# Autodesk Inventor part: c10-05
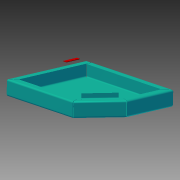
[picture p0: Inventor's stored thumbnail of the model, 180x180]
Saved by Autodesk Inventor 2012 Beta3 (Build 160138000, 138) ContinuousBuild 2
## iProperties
Created: 2011-01
Part Number: c10-05
Material: Steel, Mild
Document SubType Name: Sheet Metal
Designer: Beta-8540w
Density: 7.86 g/cm^3
Sheet Metal Rule: Steel - 16ga
Author: Beta-8540w
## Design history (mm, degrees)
node "Face1"
  sketch "Sketch1"
    geometry: L1 (0, 0)-(240, 0); L2 (240, 0)-(240, 300); L3 (240, 300)-(0, 300); L4 (0, 300)-(0, 0); L5 (140, 300)-(240, 229.979)
    constraints: 10 end point, 2 parallel, 2 point on line, 1 horizontal, 1 perpendicular
    dimensions: "d0" = 240 distance of L3.end L2.end; "d1" = 300 distance of L2.end L1.end; "d2" = 35 deg angle of L3 L5; "d3" = 100 distance from line of L2 L5.start
node "Flange1"
node "Flange2"
workplane "Work Plane1"
node "Flange3"
node "Face2"
  sketch "Sketch4"
    geometry: L1 (0, 15.428)-(214.889, 15.428) reference; L2 (25, 5.428)-(65, 5.428); L3 (65, 5.428)-(65, -4.572); L4 (65, -4.572)-(25, -4.572); L5 (25, -4.572)-(25, 5.428); 1 further point
    constraints: 8 end point, 2 parallel, 1 horizontal, 1 perpendicular
    dimensions: "d27" = 25 distance from line of L5 L1.start; "d28" = 10 distance of L4.end L2.start; "d29" = 40 distance of L3.end L4.end; "d50" = 10 distance between parallel lines of L1 L2
sketch "Sketch5" dims "SeamGap" = 0.01, "Thickness" = 1.524 (derived)
  geometry: L1 (0, 15.428)-(214.889, 15.428) reference; L2 (160, 5.428)-(200, 5.428); L3 (200, 5.428)-(200, -4.572); L4 (200, -4.572)-(160, -4.572); L5 (160, -4.572)-(160, 5.428); 1 further point
  constraints: 8 end point, 2 parallel, 1 horizontal, 1 perpendicular
  dimensions: "d30" = 10 distance of L4.end L2.start (= d28); "d31" = 40 distance of L3.end L4.end (= d29); "d32" = 160 distance from line of L1.start L5; "d51" = 10 distance between parallel lines of L1 L2
body "Solid1"
face "Plate1" dims "Thickness" = 1.524 (derived)
sketch "Sketch2"
  geometry: L1 (0, 40)-(-300, 40); L2 (-300, 40)-(-300, 0); 2 other entities
  constraints: 4 end point, 4 other
face "Plate2" dims "d5" = 1.524 (= BendReliefWidth), "d6" = 0.762 (= BendReliefDepth), "d7" = 3.048 (= MinimumRemnant), "d8" = 3.048 (= BendRadius), "d9" = 40, "d10" = 90 deg, "d11" = 3.048 (= BendRadius), "d12" = 6.096 (= CornerReliefSize), "d13" = 0.762 (= GapSize), "d14" = 3.048 (= JacobiRadiusSize), "SeamGap" = 0.01, "Thickness" = 1.524 (derived)
bend "Bend1" dims "d5" = 1.524 (= BendReliefWidth), "d6" = 0.762 (= BendReliefDepth), "d7" = 3.048 (= MinimumRemnant), "d8" = 3.048 (= BendRadius), "d9" = 40, "d10" = 90 deg, "d11" = 3.048 (= BendRadius), "SeamGap" = 0.01, "Thickness" = 1.524 (derived)
feature "Corner1" dims "d9" = 40, "d10" = 90 deg, "d12" = 6.096 (= CornerReliefSize), "d13" = 0.762 (= GapSize), "d14" = 3.048 (= JacobiRadiusSize)
sketch "Sketch3"
  geometry: L1 (20, 0)-(20, 295.874); L2 (20, 295.874)-(0, 295.874); 2 other entities
  constraints: 4 end point, 4 other
face "Plate3" dims "d15" = 1.524 (= BendReliefWidth), "d16" = 0.762 (= BendReliefDepth), "d17" = 3.048 (= MinimumRemnant), "d18" = 3.048 (= BendRadius), "d19" = 20, "d20" = 90 deg, "d21" = 3.048 (= BendRadius), "d22" = 6.096 (= CornerReliefSize), "d23" = 0.762 (= GapSize), "d24" = 3.048 (= JacobiRadiusSize), "d25" = 10, "SeamGap" = 0.01, "Thickness" = 1.524 (derived)
bend "Bend2" dims "d15" = 1.524 (= BendReliefWidth), "d16" = 0.762 (= BendReliefDepth), "d17" = 3.048 (= MinimumRemnant), "d18" = 3.048 (= BendRadius), "d19" = 20, "d20" = 90 deg, "d21" = 3.048 (= BendRadius), "SeamGap" = 0.01, "Thickness" = 1.524 (derived)
feature "Corner2" dims "d19" = 20, "d20" = 90 deg, "d22" = 6.096 (= CornerReliefSize), "d23" = 0.762 (= GapSize), "d24" = 3.048 (= JacobiRadiusSize)
face "Plate4" dims "d33" = 3.048 (= BendRadius), "d34" = 1.524 (= BendReliefWidth), "d36" = 3.048 (= MinimumRemnant), "Thickness" = 1.524 (derived)
bend "Bend3" dims "d33" = 3.048 (= BendRadius), "d34" = 1.524 (= BendReliefWidth), "d35" = 0.762 (= BendReliefDepth), "d36" = 3.048 (= MinimumRemnant), "d37" = 3.048 (= BendRadius), "SeamGap" = 0.01, "Thickness" = 1.524 (derived)
sketch "Sketch6"
  geometry: L1 (-94.531, 0)-(-10, 0); L2 (-10, 0)-(-10, 15); L3 (-10, 15)-(-94.531, 15); L4 (-94.531, 15)-(-94.531, 0)
  constraints: 8 end point
face "Plate5" dims "d38" = 1.524 (= BendReliefWidth), "d39" = 0.762 (= BendReliefDepth), "d40" = 3.048 (= MinimumRemnant), "d41" = 3.048 (= BendRadius), "d42" = 10, "d43" = 10, "d44" = 15, "d45" = 90 deg, "d46" = 3.048 (= BendRadius), "d47" = 6.096 (= CornerReliefSize), "d48" = 0.762 (= GapSize), "d49" = 3.048 (= JacobiRadiusSize), "SeamGap" = 0.01, "Thickness" = 1.524 (derived)
bend "Bend4" dims "d38" = 1.524 (= BendReliefWidth), "d39" = 0.762 (= BendReliefDepth), "d40" = 3.048 (= MinimumRemnant), "d41" = 3.048 (= BendRadius), "d44" = 15, "d45" = 90 deg, "d46" = 3.048 (= BendRadius), "SeamGap" = 0.01, "Thickness" = 1.524 (derived)
feature "Corner3" dims "d44" = 15, "d45" = 90 deg, "d47" = 6.096 (= CornerReliefSize), "d48" = 0.762 (= GapSize), "d49" = 3.048 (= JacobiRadiusSize)
other parameters: "BendRadius" = 3.048 (= 2 x Thickness), "BendReliefWidth" = 1.524 (= Thickness), "BendReliefDepth" = 0.762 (= 0.5 x Thickness), "CornerReliefSize" = 6.096 (= 4 x Thickness), "MinimumRemnant" = 3.048 (= 2 x Thickness), "TransitionRadius" = 3.048 (= BendRadius), "JacobiRadiusSize" = 3.048 (= BendRadius), "GapSize" = 0.762 (= 0.5 x Thickness), "d4" = 3.048 (= BendRadius)
